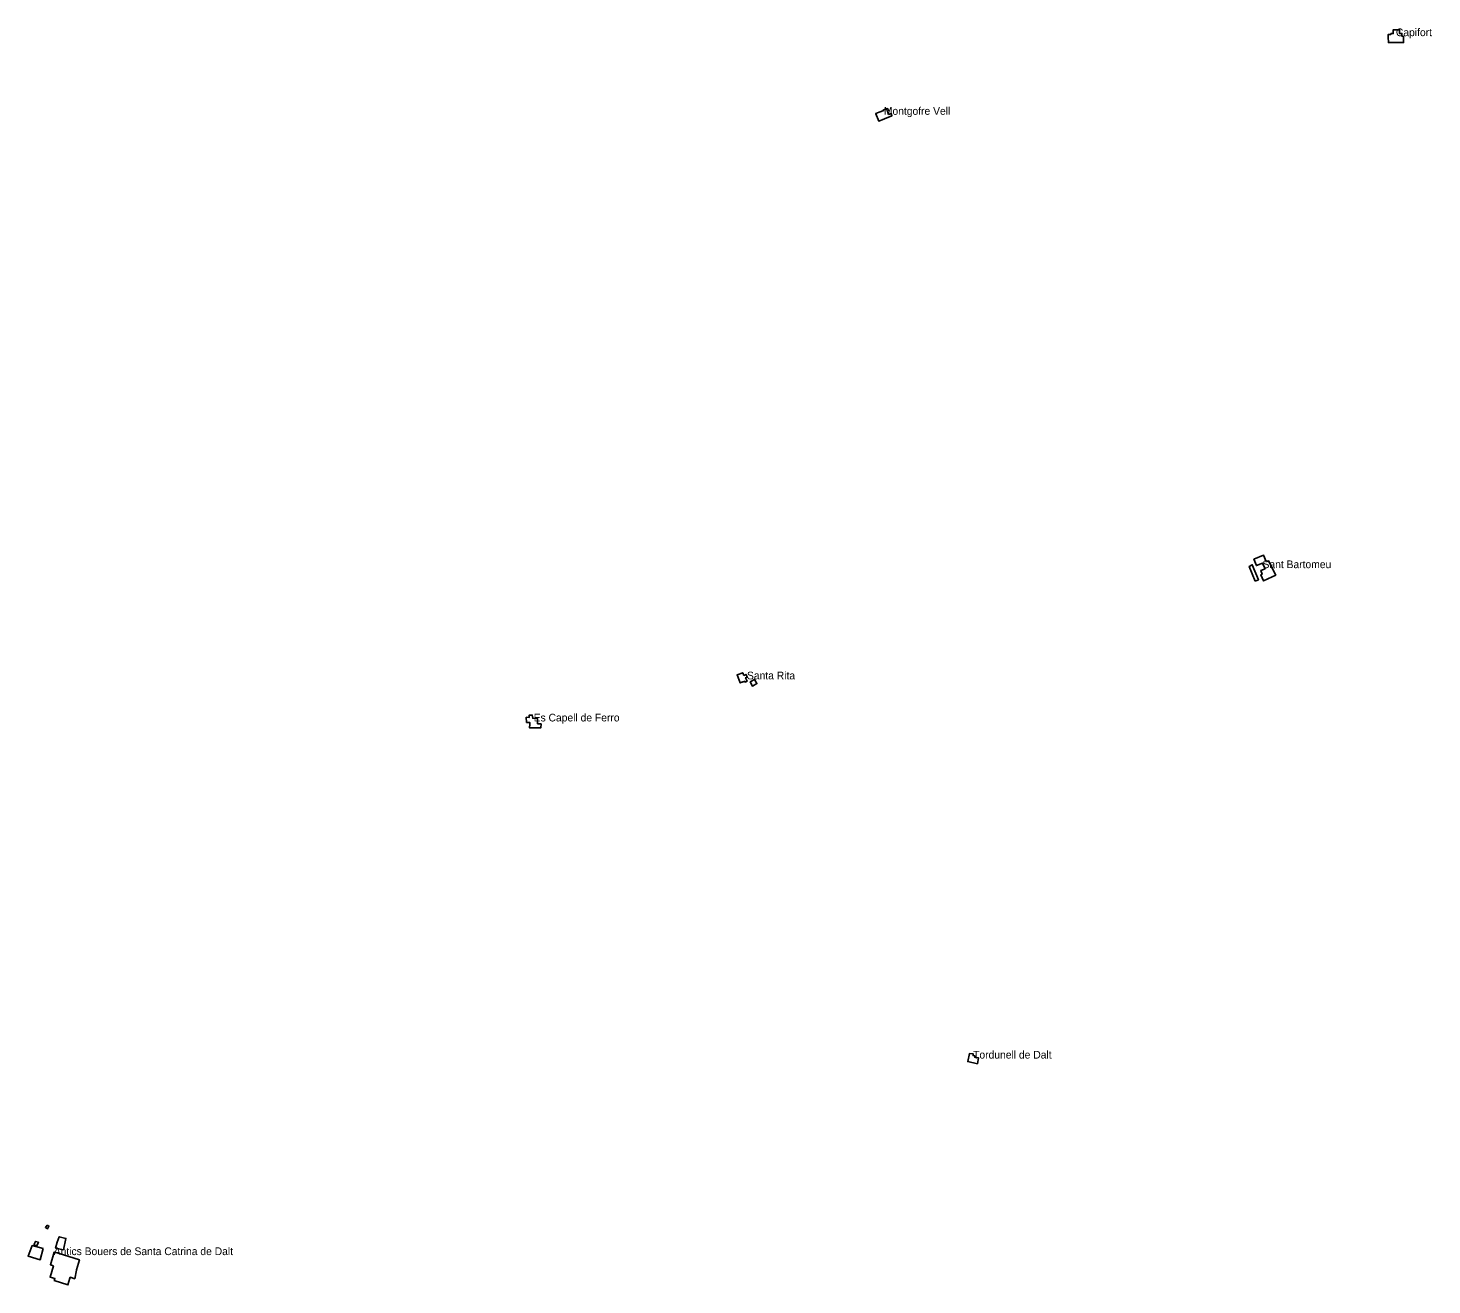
# Model space of a CAD drawing. Extents: x 599451 to 612034, y 4411179 to 4428219.
# Drawn here: x 603123 to 605309, y 4424304 to 4426261 of the extents above; entities that cross this region are included whole.
import ezdxf

# ---------------------------------------------------------------- set-up
doc = ezdxf.new("R2010")
doc.units = 0
doc.layers.add('Bé Arquitectònic', color=7, linetype='Continuous')

msp = doc.modelspace()

# ---------------------------------------------------------------- linework, layer by layer
at = {"layer": 'Bé Arquitectònic'}
for points in [[(605242.2, 4426251.3), (605240.8, 4426251.3), (605240.9, 4426247.3), (605241, 4426238.7), (605248.6, 4426238.7), (605253, 4426238.6), (605258.4, 4426238.6), (605264.6, 4426238.6), (605264.5, 4426248.6), (605262.1, 4426248.6), (605262.1, 4426253), (605258.3, 4426253.1), (605258.4, 4426258.8), (605248.6, 4426258.7), (605248.5, 4426252.7), (605245, 4426252.7), (605245, 4426251.3)], [(604448.1, 4426130.3), (604442.6, 4426128.1), (604442.9, 4426127.5), (604447.4, 4426116.4), (604452.9, 4426118.6), (604459.7, 4426121.4), (604464.2, 4426123.2), (604467.9, 4426124.7), (604466.7, 4426128.3), (604462.7, 4426126.9), (604461.5, 4426130), (604460.7, 4426132.1), (604462.4, 4426132.8), (604461.2, 4426135.9), (604454.5, 4426134), (604455, 4426133.1)], [(605060.2, 4425406.7), (605065.5, 4425409.4), (605054.3, 4425431.5), (605050.6, 4425430.5), (605046.7, 4425440.3), (605031.6, 4425434.1), (605035.4, 4425424.1), (605045.1, 4425428.1), (605048.9, 4425419.2), (605042.6, 4425416.7), (605044.4, 4425410.8), (605042.4, 4425410), (605046.3, 4425400.4)], [(605033.6, 4425400), (605038.5, 4425402), (605029, 4425425.5), (605024.4, 4425422.9)], [(604237.1, 4425253.2), (604235.4, 4425257.4), (604226.6, 4425253.9), (604231.6, 4425241.6), (604235.2, 4425243.1), (604235.3, 4425242.8), (604238.6, 4425244.2), (604239.2, 4425242.7), (604242.3, 4425244), (604240, 4425249.5), (604242.5, 4425250.5), (604240.7, 4425254.7)], [(604253.6, 4425246.7), (604247.1, 4425243), (604250.7, 4425236.6), (604257.3, 4425240.4), (604257.6, 4425240.5), (604254, 4425246.9)], [(603898.4, 4425188.1), (603899, 4425179.9), (603903.8, 4425180.1), (603903.8, 4425177.3), (603903.6, 4425171.5), (603921.2, 4425171.8), (603921.4, 4425177.6), (603916.1, 4425178), (603916.1, 4425185.9), (603908.5, 4425186.4), (603907.8, 4425191.5), (603903.1, 4425191.5), (603903.1, 4425187.8)], [(604601.1, 4424648.5), (604602.8, 4424657.4), (604596.9, 4424658.6), (604597.2, 4424660.6), (604594.2, 4424661), (604594.4, 4424663.6), (604588.9, 4424664.5), (604585.8, 4424651.7)], [(603152, 4424396.9), (603149.6, 4424393.5), (603153, 4424391.5), (603155.1, 4424395.5)], [(603177.5, 4424358.6), (603181.4, 4424376.4), (603171.2, 4424378.9), (603169.3, 4424374.6), (603167.6, 4424370.5), (603165.3, 4424361.2)], [(603146, 4424360.6), (603129, 4424365.2), (603122.5, 4424348.9), (603141.6, 4424343.1)], [(603131.7, 4424366.3), (603136.2, 4424364.7), (603138.6, 4424370.5), (603134.3, 4424371.8)], [(603162.2, 4424333.9), (603156.7, 4424316.3), (603164.2, 4424313.9), (603163.4, 4424310.6), (603184.5, 4424304), (603187.6, 4424314.6), (603188.1, 4424315.9), (603195.1, 4424313.7), (603198.1, 4424326.7), (603198.3, 4424327.5), (603197.8, 4424327.7), (603202.5, 4424342.8), (603169.2, 4424353.4), (603163.4, 4424355.2), (603157.2, 4424335.4)]]:
    msp.add_lwpolyline(points, close=True, dxfattribs=at)

# ---------------------------------------------------------------- texts
for s, p in [('Capifort', (605252.7, 4426248.7)), ('Montgofre Vell', (604455.3, 4426126.2)), ('Sant Bartomeu', (605045, 4425420.2)), ('Santa Rita', (604242.1, 4425247)), ('Es Capell de Ferro', (603909.9, 4425181.5)), ('Tordunell de Dalt', (604594.3, 4424656.5)), ('Antics Bouers de Santa Catrina de Dalt', (603162.5, 4424350.4))]:
    msp.add_text(s, height=12, dxfattribs=at).set_placement(p)

doc.saveas('drawing.dxf')
